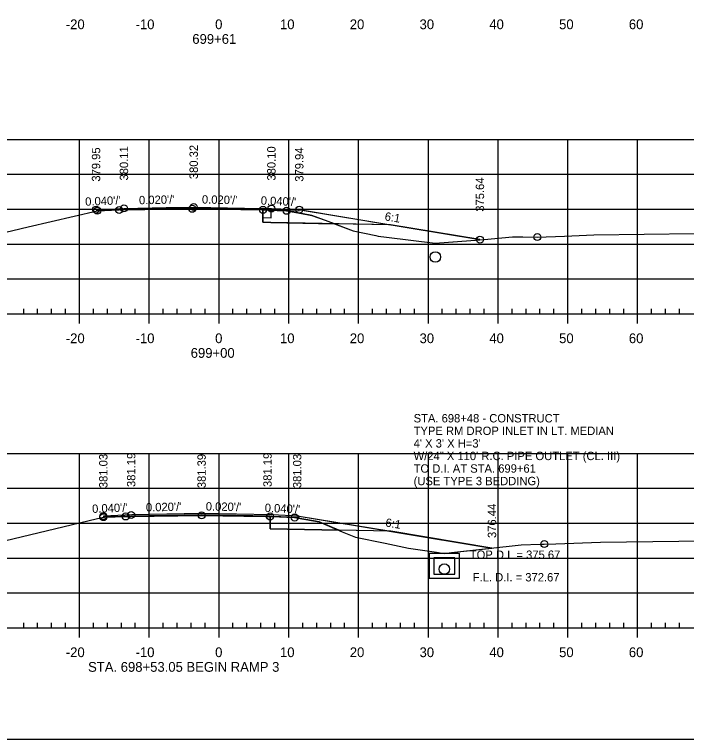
# Model space of a CAD drawing. Extents: x 1359801 to 1362404, y 372415 to 374228.
# Drawn here: x 1361174.4 to 1361270.7, y 372525.2 to 372629.2 of the extents above; entities that cross this region are included whole.
import ezdxf

# ---------------------------------------------------------------- set-up
doc = ezdxf.new("R2010")
doc.units = 0
for name, color, linetype in [('S_DRG_PT_SYM', 7, 'Continuous'), ('S_ELECTRIC_UTILITIES_ANNOT', 7, 'Continuous'), ('S_IRON_PIN', 7, 'Continuous'), ('S_MAILBOX', 7, 'Continuous'), ('S_PRIMARY_CTL', 7, 'Continuous'), ('S_SANITARY_SEWER', 7, 'Continuous'), ('S_SHOULDER', 7, 'Continuous'), ('S_UNDERGROUND_CABLE', 7, 'Continuous'), ('S_UTILITY_POLE_ANNOT', 7, 'Continuous'), ('S_UTL_PT_SYM', 7, 'Continuous'), ('S_WATER_UTILITIES', 7, 'Continuous')]:
    doc.layers.add(name, color=color, linetype=linetype)

msp = doc.modelspace()

# ---------------------------------------------------------------- linework, layer by layer
at = {"layer": 'S_DRG_PT_SYM'}
for points in [[(1361170.89, 372597.44), (1361176.36, 372598.72), (1361186.25, 372601.04), (1361188.32, 372601.1), (1361189.4, 372601.14), (1361193.08, 372601.2), (1361199.87, 372601.31), (1361203.65, 372601.25), (1361210.01, 372601.16), (1361212.06, 372601.08), (1361213.4, 372601.02), (1361215.54, 372600.64), (1361217.01, 372600.37), (1361218.91, 372599.68), (1361222.92, 372598.15), (1361226.18, 372597.46), (1361226.51, 372597.39), (1361227.72, 372597.25), (1361234.68, 372596.38), (1361241.69, 372596.93), (1361245.79, 372597.3), (1361247.25, 372597.29), (1361249.33, 372597.25), (1361253.22, 372597.4), (1361257.44, 372597.56), (1361271.85, 372597.79)], [(1361171.93, 372553.48), (1361186.12, 372556.87), (1361187.14, 372557.11), (1361187.29, 372557.11), (1361190.33, 372557.21), (1361191.01, 372557.22), (1361201.21, 372557.37), (1361210.3, 372557.22), (1361211.02, 372557.21), (1361211.28, 372557.2), (1361214.55, 372557.06), (1361215.07, 372556.97), (1361218.04, 372556.46), (1361221.37, 372555.03), (1361223.27, 372554.24), (1361227.54, 372553.37), (1361230.88, 372552.69), (1361234.9, 372552.08), (1361236, 372551.92), (1361237.03, 372552.03), (1361246.99, 372553.17), (1361249.72, 372553.23), (1361250.33, 372553.26), (1361251.99, 372553.31), (1361258.38, 372553.53), (1361269.6, 372553.65), (1361284.58, 372553.82)]]:
    msp.add_lwpolyline(points, dxfattribs=at)
at = {"layer": 'S_ELECTRIC_UTILITIES_ANNOT'}
for p, q in [((1361210.01, 372601.16), (1361210.01, 372601.2)), ((1361210.01, 372601.16), (1361210.01, 372599.37)), ((1361228.3, 372599.01), (1361220.24, 372599.17)), ((1361220.24, 372599.17), (1361220.24, 372599.17)), ((1361241.1, 372596.88), (1361241.1, 372596.89)), ((1361211.02, 372557.21), (1361211.02, 372557.27)), ((1361211.02, 372557.21), (1361211.02, 372555.44)), ((1361211.02, 372555.44), (1361220.89, 372555.24)), ((1361228.34, 372555.09), (1361220.89, 372555.24)), ((1361220.89, 372555.24), (1361221.37, 372555.03)), ((1361242.8, 372552.69), (1361228.34, 372555.09))]:
    msp.add_line(p, q, dxfattribs=at)
for points in [[(1361210.01, 372601.2), (1361200.08, 372601.4), (1361190.08, 372601.19), (1361186.29, 372601.04)], [(1361186.29, 372601.04), (1361188.32, 372601.1), (1361189.4, 372601.14), (1361193.08, 372601.2), (1361199.87, 372601.31), (1361203.65, 372601.25), (1361210.01, 372601.16)], [(1361220.24, 372599.17), (1361217.01, 372600.37), (1361215.54, 372600.64), (1361213.4, 372601.02), (1361212.06, 372601.08), (1361210.01, 372601.16)], [(1361210.01, 372599.37), (1361211.15, 372599.35), (1361220.24, 372599.17)], [(1361220.24, 372599.17), (1361222.92, 372598.15), (1361226.18, 372597.46), (1361226.51, 372597.39), (1361227.72, 372597.25), (1361234.68, 372596.38), (1361241.1, 372596.88)], [(1361241.1, 372596.89), (1361228.3, 372599.01), (1361228.3, 372599.01)], [(1361211.02, 372557.27), (1361201.22, 372557.46), (1361191.22, 372557.26), (1361187.99, 372557.14)], [(1361187.99, 372557.14), (1361190.33, 372557.21), (1361191.01, 372557.22), (1361201.21, 372557.37), (1361210.3, 372557.22), (1361211.02, 372557.21)], [(1361220.89, 372555.24), (1361218.04, 372556.46), (1361215.07, 372556.97), (1361214.55, 372557.06), (1361211.28, 372557.2), (1361211.02, 372557.21)], [(1361221.37, 372555.03), (1361223.27, 372554.24), (1361227.54, 372553.37), (1361230.88, 372552.69), (1361234.9, 372552.08), (1361236, 372551.92), (1361237.03, 372552.03), (1361242.8, 372552.69)]]:
    msp.add_lwpolyline(points, dxfattribs=at)
at = {"layer": 'S_MAILBOX'}
for p, q in [((1361058.71, 372611.25), (1361348.71, 372611.25)), ((1361183.71, 372586.25), (1361183.71, 372611.25)), ((1361193.71, 372586.25), (1361193.71, 372611.25)), ((1361203.71, 372586.25), (1361203.71, 372611.25)), ((1361213.71, 372586.25), (1361213.71, 372611.25)), ((1361223.71, 372586.25), (1361223.71, 372611.25)), ((1361233.71, 372586.25), (1361233.71, 372611.25)), ((1361243.71, 372586.25), (1361243.71, 372611.25)), ((1361253.71, 372586.25), (1361253.71, 372611.25)), ((1361263.71, 372586.25), (1361263.71, 372611.25)), ((1361058.71, 372606.25), (1361348.71, 372606.25)), ((1361058.71, 372601.25), (1361348.71, 372601.25)), ((1361058.71, 372596.25), (1361348.71, 372596.25)), ((1361058.71, 372591.25), (1361348.71, 372591.25)), ((1361058.71, 372586.25), (1361348.71, 372586.25)), ((1361058.71, 372566.25), (1361348.71, 372566.25)), ((1361183.71, 372541.25), (1361183.71, 372566.25)), ((1361193.71, 372541.25), (1361193.71, 372566.25)), ((1361203.71, 372541.25), (1361203.71, 372566.25)), ((1361213.71, 372541.25), (1361213.71, 372566.25)), ((1361223.71, 372541.25), (1361223.71, 372566.25)), ((1361233.71, 372541.25), (1361233.71, 372566.25)), ((1361243.71, 372541.25), (1361243.71, 372566.25)), ((1361253.71, 372541.25), (1361253.71, 372566.25)), ((1361263.71, 372541.25), (1361263.71, 372566.25)), ((1361058.71, 372561.25), (1361348.71, 372561.25)), ((1361058.71, 372556.25), (1361348.71, 372556.25)), ((1361058.71, 372551.25), (1361348.71, 372551.25)), ((1361058.71, 372546.25), (1361348.71, 372546.25)), ((1361058.71, 372541.25), (1361348.71, 372541.25))]:
    msp.add_line(p, q, dxfattribs=at)
at = {"layer": 'S_SANITARY_SEWER'}
msp.add_line((1361215.21, 372557.27), (1361242.8, 372552.69), dxfattribs=at)
for points in [[(1361186.08, 372601.19), (1361186.08, 372601.19), (1361186.08, 372601.2), (1361186.29, 372601.2), (1361190.08, 372601.36), (1361196.15, 372601.48), (1361200.08, 372601.56), (1361200.08, 372601.56), (1361200.08, 372601.56), (1361209.8, 372601.37), (1361211.21, 372601.35), (1361211.22, 372601.35), (1361215.21, 372601.19), (1361215.32, 372601.17), (1361224.89, 372599.58), (1361225.46, 372599.49), (1361241.1, 372596.89)], [(1361215.21, 372557.27), (1361211.21, 372557.43), (1361201.22, 372557.63), (1361201.22, 372557.63), (1361191.22, 372557.43), (1361191.22, 372557.43), (1361187.22, 372557.27)], [(1361187.12, 372557.27), (1361187.14, 372557.27)]]:
    msp.add_lwpolyline(points, dxfattribs=at)
at = {"layer": 'S_SHOULDER'}
msp.add_line((1361187.13, 372557.1), (1361187.14, 372557.1), dxfattribs=at)
msp.add_lwpolyline([(1361279.63, 372730.71), (1361279.63, 372720.83), (1361315.36, 372720.83), (1361315.36, 372717.91), (1361338.56, 372717.91), (1361338.56, 372693.57), (1361361.89, 372693.57), (1361361.89, 372525.25), (1361045.71, 372525.25), (1361045.71, 372730.71)], close=True, dxfattribs=at)
for points in [[(1361210.01, 372600.04), (1361211.19, 372600.02), (1361211.2, 372601.18)], [(1361211.2, 372601.18), (1361215.19, 372601.02), (1361215.21, 372601.19), (1361228.3, 372599.01)], [(1361228.3, 372599.01), (1361211.15, 372599.35), (1361210.01, 372599.37), (1361210.01, 372600.04)], [(1361228.34, 372555.09), (1361211.02, 372555.44), (1361211.02, 372557.27)], [(1361211.02, 372557.27), (1361211.21, 372557.26), (1361215.2, 372557.11), (1361215.21, 372557.27), (1361228.34, 372555.09)]]:
    msp.add_lwpolyline(points, dxfattribs=at)
for centre in [(1361200.08, 372601.56), (1361186.08, 372601.2), (1361186.25, 372601.04), (1361189.4, 372601.14), (1361190.08, 372601.36), (1361199.87, 372601.31), (1361210.01, 372601.16), (1361211.21, 372601.35), (1361213.4, 372601.02), (1361215.21, 372601.19), (1361241.1, 372596.89), (1361249.33, 372597.25), (1361187.12, 372557.27), (1361187.14, 372557.11), (1361190.33, 372557.21), (1361191.12, 372557.43), (1361201.21, 372557.37), (1361211.02, 372557.21), (1361214.55, 372557.06), (1361250.33, 372553.26)]:
    msp.add_circle(centre, 0.5, dxfattribs=at)
at = {"layer": 'S_UNDERGROUND_CABLE'}
for points in [[(1361228.3, 372599.01), (1361211.15, 372599.35), (1361210.01, 372599.37), (1361210.01, 372601.2), (1361200.08, 372601.4), (1361190.08, 372601.19), (1361186.08, 372601.03)], [(1361211.02, 372557.27), (1361201.22, 372557.46), (1361191.22, 372557.26), (1361187.23, 372557.11)], [(1361228.34, 372555.09), (1361211.02, 372555.44), (1361211.02, 372557.27)]]:
    msp.add_lwpolyline(points, dxfattribs=at)
at = {"layer": 'S_UTILITY_POLE_ANNOT'}
for p, q in [((1361238.17, 372551.92), (1361233.84, 372551.92)), ((1361237.5, 372551.26), (1361234.5, 372551.26))]:
    msp.add_line(p, q, dxfattribs=at)
for points in [[(1361233.84, 372551.92), (1361233.84, 372548.39), (1361238.17, 372548.39), (1361238.17, 372551.92)], [(1361234.5, 372551.26), (1361234.5, 372548.92), (1361237.5, 372548.92), (1361237.5, 372551.26)]]:
    msp.add_lwpolyline(points, dxfattribs=at)
for centre in [(1361234.71, 372594.4), (1361236, 372549.67)]:
    msp.add_circle(centre, 0.75, dxfattribs=at)
at = {"layer": 'S_UTL_PT_SYM'}
msp.add_line((1361361.89, 372525.25), (1361045.71, 372525.25), dxfattribs=at)
at = {"layer": 'S_WATER_UTILITIES'}
for p, q in [((1361175.71, 372586.25), (1361175.71, 372586.95)), ((1361177.71, 372586.25), (1361177.71, 372586.95)), ((1361179.71, 372586.25), (1361179.71, 372586.95)), ((1361181.71, 372586.25), (1361181.71, 372586.95)), ((1361185.71, 372586.25), (1361185.71, 372586.95)), ((1361187.71, 372586.25), (1361187.71, 372586.95)), ((1361189.71, 372586.25), (1361189.71, 372586.95)), ((1361191.71, 372586.25), (1361191.71, 372586.95)), ((1361195.71, 372586.25), (1361195.71, 372586.95)), ((1361197.71, 372586.25), (1361197.71, 372586.95)), ((1361199.71, 372586.25), (1361199.71, 372586.95)), ((1361201.71, 372586.25), (1361201.71, 372586.95)), ((1361205.71, 372586.25), (1361205.71, 372586.95)), ((1361207.71, 372586.25), (1361207.71, 372586.95)), ((1361209.71, 372586.25), (1361209.71, 372586.95)), ((1361211.71, 372586.25), (1361211.71, 372586.95)), ((1361215.71, 372586.25), (1361215.71, 372586.95)), ((1361217.71, 372586.25), (1361217.71, 372586.95)), ((1361219.71, 372586.25), (1361219.71, 372586.95)), ((1361221.71, 372586.25), (1361221.71, 372586.95)), ((1361225.71, 372586.25), (1361225.71, 372586.95)), ((1361227.71, 372586.25), (1361227.71, 372586.95)), ((1361229.71, 372586.25), (1361229.71, 372586.95)), ((1361231.71, 372586.25), (1361231.71, 372586.95)), ((1361235.71, 372586.25), (1361235.71, 372586.95)), ((1361237.71, 372586.25), (1361237.71, 372586.95)), ((1361239.71, 372586.25), (1361239.71, 372586.95)), ((1361241.71, 372586.25), (1361241.71, 372586.95)), ((1361245.71, 372586.25), (1361245.71, 372586.95)), ((1361247.71, 372586.25), (1361247.71, 372586.95)), ((1361249.71, 372586.25), (1361249.71, 372586.95)), ((1361251.71, 372586.25), (1361251.71, 372586.95)), ((1361255.71, 372586.25), (1361255.71, 372586.95)), ((1361257.71, 372586.25), (1361257.71, 372586.95)), ((1361259.71, 372586.25), (1361259.71, 372586.95)), ((1361261.71, 372586.25), (1361261.71, 372586.95)), ((1361265.71, 372586.25), (1361265.71, 372586.95)), ((1361267.71, 372586.25), (1361267.71, 372586.95)), ((1361269.71, 372586.25), (1361269.71, 372586.95)), ((1361058.71, 372586.25), (1361348.71, 372586.25)), ((1361183.71, 372584.85), (1361183.71, 372586.25)), ((1361193.71, 372584.85), (1361193.71, 372586.25)), ((1361203.71, 372584.85), (1361203.71, 372586.25)), ((1361213.71, 372584.85), (1361213.71, 372586.25)), ((1361223.71, 372584.85), (1361223.71, 372586.25)), ((1361233.71, 372584.85), (1361233.71, 372586.25)), ((1361243.71, 372584.85), (1361243.71, 372586.25)), ((1361253.71, 372584.85), (1361253.71, 372586.25)), ((1361263.71, 372584.85), (1361263.71, 372586.25)), ((1361175.71, 372541.25), (1361175.71, 372541.95)), ((1361177.71, 372541.25), (1361177.71, 372541.95)), ((1361179.71, 372541.25), (1361179.71, 372541.95)), ((1361181.71, 372541.25), (1361181.71, 372541.95)), ((1361185.71, 372541.25), (1361185.71, 372541.95)), ((1361187.71, 372541.25), (1361187.71, 372541.95)), ((1361189.71, 372541.25), (1361189.71, 372541.95)), ((1361191.71, 372541.25), (1361191.71, 372541.95)), ((1361195.71, 372541.25), (1361195.71, 372541.95)), ((1361197.71, 372541.25), (1361197.71, 372541.95)), ((1361199.71, 372541.25), (1361199.71, 372541.95)), ((1361201.71, 372541.25), (1361201.71, 372541.95)), ((1361205.71, 372541.25), (1361205.71, 372541.95)), ((1361207.71, 372541.25), (1361207.71, 372541.95)), ((1361209.71, 372541.25), (1361209.71, 372541.95)), ((1361211.71, 372541.25), (1361211.71, 372541.95)), ((1361215.71, 372541.25), (1361215.71, 372541.95)), ((1361217.71, 372541.25), (1361217.71, 372541.95)), ((1361219.71, 372541.25), (1361219.71, 372541.95)), ((1361221.71, 372541.25), (1361221.71, 372541.95)), ((1361225.71, 372541.25), (1361225.71, 372541.95)), ((1361227.71, 372541.25), (1361227.71, 372541.95)), ((1361229.71, 372541.25), (1361229.71, 372541.95)), ((1361231.71, 372541.25), (1361231.71, 372541.95)), ((1361235.71, 372541.25), (1361235.71, 372541.95)), ((1361237.71, 372541.25), (1361237.71, 372541.95)), ((1361239.71, 372541.25), (1361239.71, 372541.95)), ((1361241.71, 372541.25), (1361241.71, 372541.95)), ((1361245.71, 372541.25), (1361245.71, 372541.95)), ((1361247.71, 372541.25), (1361247.71, 372541.95)), ((1361249.71, 372541.25), (1361249.71, 372541.95)), ((1361251.71, 372541.25), (1361251.71, 372541.95)), ((1361255.71, 372541.25), (1361255.71, 372541.95)), ((1361257.71, 372541.25), (1361257.71, 372541.95)), ((1361259.71, 372541.25), (1361259.71, 372541.95)), ((1361261.71, 372541.25), (1361261.71, 372541.95)), ((1361265.71, 372541.25), (1361265.71, 372541.95)), ((1361267.71, 372541.25), (1361267.71, 372541.95)), ((1361269.71, 372541.25), (1361269.71, 372541.95)), ((1361058.71, 372541.25), (1361348.71, 372541.25)), ((1361183.71, 372539.85), (1361183.71, 372541.25)), ((1361193.71, 372539.85), (1361193.71, 372541.25)), ((1361203.71, 372539.85), (1361203.71, 372541.25)), ((1361213.71, 372539.85), (1361213.71, 372541.25)), ((1361223.71, 372539.85), (1361223.71, 372541.25)), ((1361233.71, 372539.85), (1361233.71, 372541.25)), ((1361243.71, 372539.85), (1361243.71, 372541.25)), ((1361253.71, 372539.85), (1361253.71, 372541.25)), ((1361263.71, 372539.85), (1361263.71, 372541.25))]:
    msp.add_line(p, q, dxfattribs=at)

# ---------------------------------------------------------------- texts
at = {"layer": 'S_IRON_PIN'}
for s, rotation, p in [('380.32', 90, (1361200.68, 372605.56)), ('379.95', 90, (1361186.68, 372605.2)), ('380.11', 90, (1361190.68, 372605.36)), ('380.10', 90, (1361211.81, 372605.35)), ('379.94', 90, (1361215.81, 372605.19)), ('375.64', 90, (1361241.7, 372600.89)), ("0.040'/'", 2.2919, (1361184.55, 372601.74)), ("0.020'/'", 1.2209, (1361192.25, 372601.95)), ("0.020'/'", 358.8849, (1361201.25, 372602.06)), ("0.040'/'", 357.7378, (1361209.67, 372601.91)), ('6:1', 350.5626, (1361227.39, 372599.67)), ('381.03', 90, (1361187.72, 372561.27)), ('381.19', 90, (1361191.72, 372561.43)), ('381.39', 90, (1361201.81, 372561.27)), ('381.19', 90, (1361211.26, 372561.43)), ('381.03', 90, (1361215.51, 372561.27)), ("0.040'/'", 2.2919, (1361185.54, 372557.71)), ("0.020'/'", 1.2209, (1361193.24, 372557.92)), ("0.020'/'", 358.8849, (1361201.8, 372558.07)), ("0.040'/'", 357.7378, (1361210.24, 372557.86)), ('376.44', 90, (1361243.43, 372554.12)), ('6:1', 350.5626, (1361227.49, 372555.79))]:
    msp.add_text(s, height=1.2, rotation=rotation, dxfattribs=at).set_placement(p)
at = {"layer": 'S_PRIMARY_CTL'}
for s, p in [('-20', (1361181.75, 372627.05)), ('-10', (1361191.75, 372627.05)), ('0', (1361203.15, 372627.05)), ('10', (1361212.45, 372627.05)), ('20', (1361222.45, 372627.05)), ('30', (1361232.45, 372627.05)), ('40', (1361242.45, 372627.05)), ('50', (1361252.45, 372627.05)), ('60', (1361262.45, 372627.05)), ('699+61', (1361199.88, 372624.95)), ('-20', (1361181.75, 372582.05)), ('-10', (1361191.75, 372582.05)), ('0', (1361203.15, 372582.05)), ('10', (1361212.45, 372582.05)), ('20', (1361222.45, 372582.05)), ('30', (1361232.45, 372582.05)), ('40', (1361242.45, 372582.05)), ('50', (1361252.45, 372582.05)), ('60', (1361262.45, 372582.05)), ('699+00', (1361199.65, 372579.95)), ('-20', (1361181.75, 372537.05)), ('-10', (1361191.75, 372537.05)), ('0', (1361203.15, 372537.05)), ('10', (1361212.45, 372537.05)), ('20', (1361222.45, 372537.05)), ('30', (1361232.45, 372537.05)), ('40', (1361242.45, 372537.05)), ('50', (1361252.45, 372537.05)), ('60', (1361262.45, 372537.05)), ('STA. 698+53.05 BEGIN RAMP 3', (1361184.94, 372534.95))]:
    msp.add_text(s, height=1.4, dxfattribs=at).set_placement(p)
at = {"layer": 'S_SHOULDER'}
for p in [(1361257.4, 372597.51), (1361258.33, 372553.48)]:
    msp.add_text('+', height=0.1, dxfattribs=at).set_placement(p)
at = {"layer": 'S_UTILITY_POLE_ANNOT'}
for s, p in [('STA. 698+48 - CONSTRUCT', (1361231.6, 372570.69)), ('TYPE RM DROP INLET IN LT. MEDIAN', (1361231.6, 372568.89)), ("4' X 3' X H=3'", (1361231.6, 372567.09)), ('W/24" X 110\' R.C. PIPE OUTLET (CL. III)', (1361231.6, 372565.29)), ('TO D.I. AT STA. 699+61', (1361231.6, 372563.49)), ('(USE TYPE 3 BEDDING)', (1361231.6, 372561.69)), ('TOP D.I. = 375.67', (1361239.65, 372551.13)), ('F.L. D.I. = 372.67', (1361240.07, 372547.9))]:
    msp.add_text(s, height=1.2, dxfattribs=at).set_placement(p)

doc.saveas('drawing.dxf')
